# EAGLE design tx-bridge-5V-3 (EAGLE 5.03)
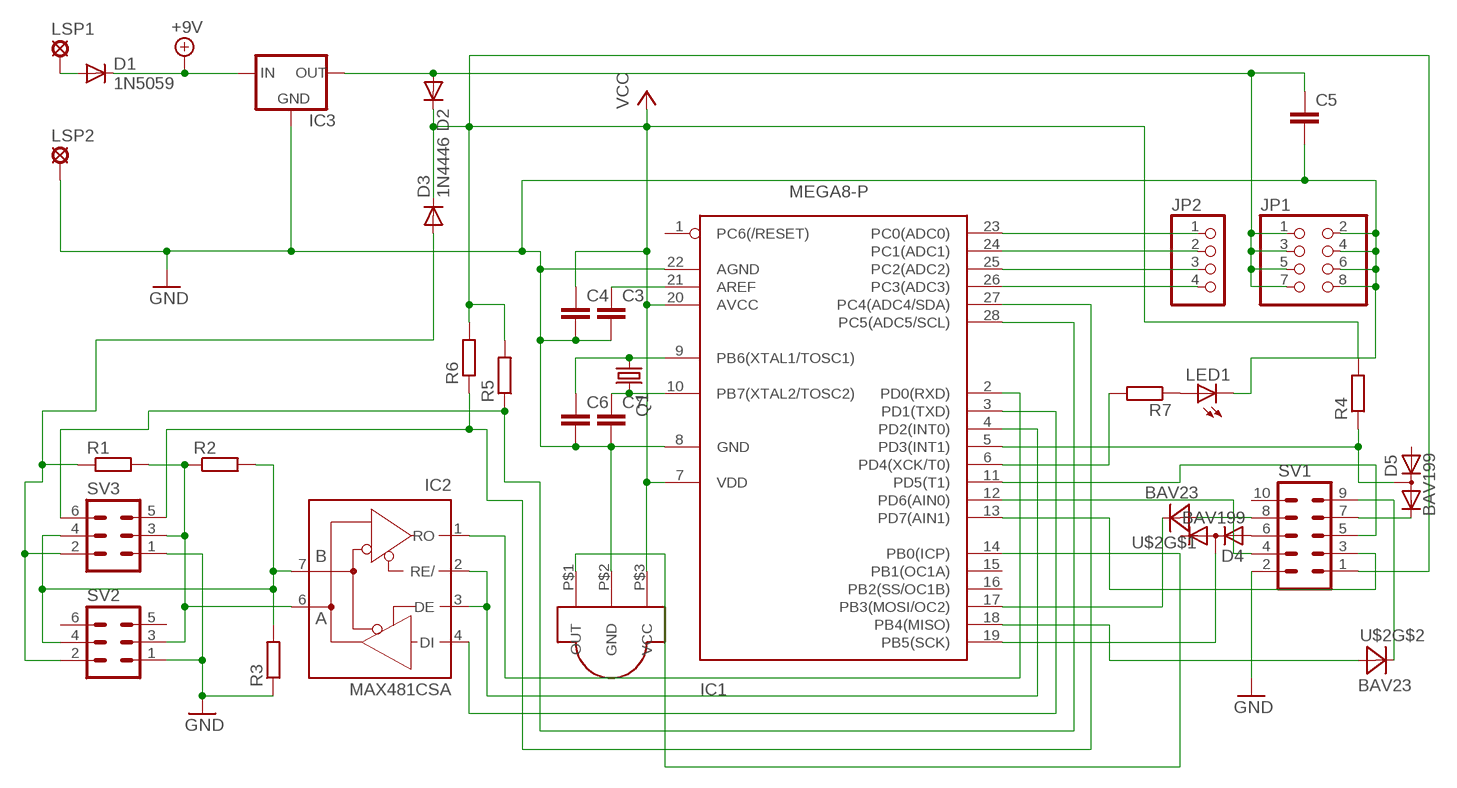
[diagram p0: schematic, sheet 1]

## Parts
C3  C-EUC0805  [C0805]
C4  C-EUC0805  [C0805]
C5  C-EUC0805  [C0805]
C6  C-EUC0805  [C0805]
C7  C-EUC0805  [C0805]
D1  1N5059  [DO204-10]
D2  DIODE-DO214AC  [DO214AC]
D3  1N4446  [DO35-10]
D4  BAV199  [SOT23]
D5  BAV199  [SOT23]
IC1  MEGA8-P  [DIL28-3]
IC2  MAX481CSA  [SO08]
IC3  78XXL  [78XXL]
JP1  PINHD-2X4  [2X04]
JP2  PINHD-1X4  [1X04]
LED1  LEDCHIP-LED0805  [CHIP-LED0805]
LSP1  LSP10  [LSP10]
LSP2  LSP10  [LSP10]
Q1  CRYSTALHC49S  [HC49/S]
R1  R-EU_R0805  [R0805]
R2  R-EU_R0805  [R0805]
R3  R-EU_R0805  [R0805]
R4  R-EU_R0805  [R0805]
R5  R-EU_R0805  [R0805]
R6  R-EU_R0805  [R0805]
R7  R-EU_R0805  [R0805]
SV1  ML10  [ML10]
SV2  ML6  [ML6]
SV3  ML6  [ML6]
U$1  SFH5110-XX  [SFH5110-XX]
U$2  BAV23  [SOT143-R]

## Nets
+9V: D1.C IC3.IN
GND: C3.2 C4.2 C5.2 C6.2 C7.2 IC1.8(GND) IC1.22(AGND) IC3.GND JP1.2 JP1.4 JP1.6 JP1.8 LED1.C LSP2.MP R3.1 SV1.2 SV2.1 SV3.1 U$1.P$2(GND)
N$1: D1.A LSP1.MP
N$3: C5.1 D2.A IC3.OUT JP1.1 JP1.3 JP1.5 JP1.7
N$4: D5.2(C) SV1.7
N$5: IC2.7(B) R2.2 R3.2 SV2.4 SV3.4
N$6: D3.A R1.1 SV2.2 SV3.2
N$7: IC2.6(A) R1.2 R2.1 SV2.3 SV3.3
N$8: C7.1 IC1.10(PB7(XTAL2/TOSC2)) Q1.2
N$9: C6.1 IC1.9(PB6(XTAL1/TOSC1)) Q1.1
N$10: D5.3(AC) IC1.5(PD3(INT1)) R4.1
N$12: IC1.4(PD2(INT0)) IC2.2(RE/) IC2.3(DE)
N$13: IC1.3(PD1(TXD)) IC2.4(DI)
N$14: IC1.2(PD0(RXD)) IC2.1(RO)
N$15: IC1.17(PB3(MOSI/OC2)) U$2.1(C)
N$16: D4.1(A) SV1.6
N$17: C3.1 IC1.21(AREF)
N$18: D4.3(AC) IC1.19(PB5(SCK))
N$19: IC1.12(PD6(AIN0)) SV1.4
N$20: IC1.23(PC0(ADC0)) JP2.1
N$21: IC1.24(PC1(ADC1)) JP2.2
N$22: IC1.25(PC2(ADC2)) JP2.3
N$23: IC1.26(PC3(ADC3)) JP2.4
N$24: IC1.13(PD7(AIN1)) SV1.3
N$25: IC1.11(PD5(T1)) SV1.5
N$26: IC1.18(PB4(MISO)) U$2.3(A)
N$27: IC1.27(PC4(ADC4/SDA)) R6.1 SV3.5
N$28: SV1.9 U$2.2(C)
N$29: IC1.28(PC5(ADC5/SCL)) R5.1 SV3.6
N$30: SV1.8 U$2.4(A)
N$31: IC1.14(PB0(ICP)) U$1.P$1(OUT)
N$32: LED1.A R7.1
N$33: IC1.6(PD4(XCK/T0)) R7.2
VCC: C4.1 D2.C D3.C IC1.7(VDD) IC1.20(AVCC) R4.2 R5.2 R6.2 SV1.1 U$1.P$3(VCC)
Unconnected: D4.2(C) D5.1(A) IC1.1(PC6(/RESET)) IC1.15(PB1(OC1A)) IC1.16(PB2(SS/OC1B)) SV1.10 SV2.5 SV2.6

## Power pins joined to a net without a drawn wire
GND: IC2.5(GND)
VCC: IC2.8(VCC)

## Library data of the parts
C3-C7 = rcl:C-EU: CAPACITOR, European symbol
D1 = diode:1N5059: DIODE
D2 = diode:DIODE-: DIODE
D3 = diode:1N4446: DIODE
D4 D5 = diode:BAV199: DIODE low-leakage double diode
IC1 = atmel:MEGA8-P: MICROCONTROLLER 8 Kbytes FLASH, 1 kbytes SRAM, 512 bytes EEPROM, USART, 4-channel 10 bit ADC, 2-channel 8 bit ADC Pin compatible with Atmega48, ATMega88, ATMega168 Source: avr.lbr
IC2 = maxim:MAX481CSA: RS485 TRANSEIVER
IC3 = v-reg-3:78XXL: VOLTAGE REGULATOR
JP1 = pinhead:PINHD-2X4: PIN HEADER
JP2 = pinhead:PINHD-1X4: PIN HEADER
LED1 = led:LED: LED
LSP1 LSP2 = solpad:LSP10: SOLDER PAD
Q1 = crystal:CRYSTAL: CRYSTAL
R1-R7 = rcl:R-EU_: RESISTOR, European symbol
SV1 = con-harting-ml:ML10: HARTING
SV2 SV3 = con-harting-ml:ML6: HARTING
U$1 = myown:SFH5110-XX
U$2 = diode:BAV23

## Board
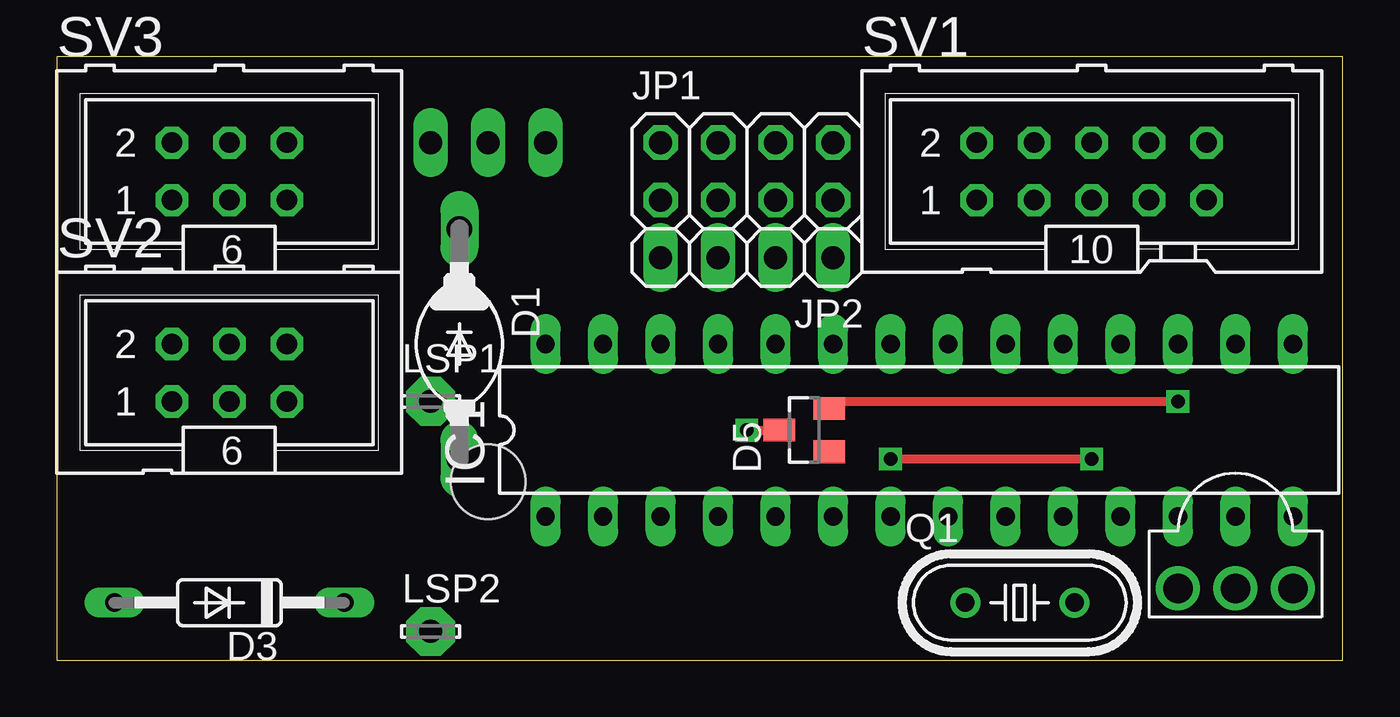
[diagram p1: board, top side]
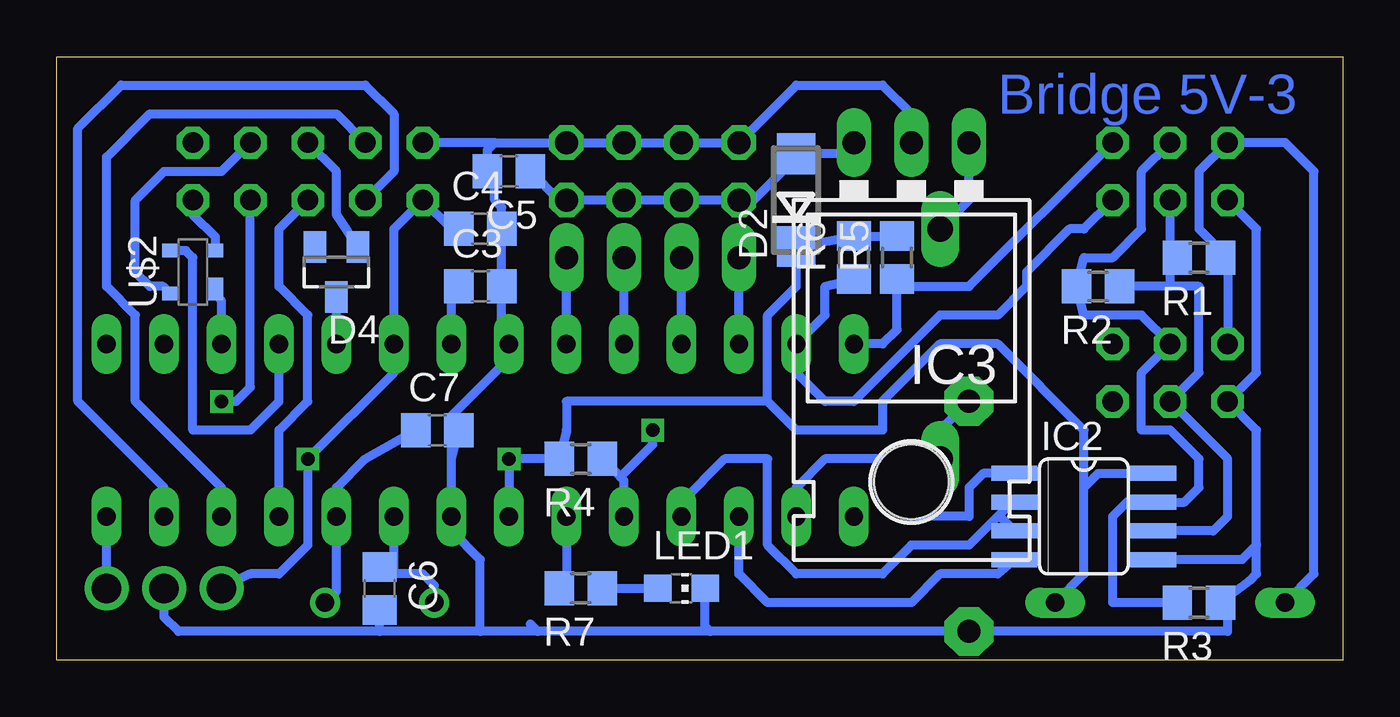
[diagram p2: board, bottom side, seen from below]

Size 56.82 x 26.66 mm. Coordinates in mm from the lower left corner, seen from the top.
Outline: 0,0 56.82,0 56.82,26.66 0,26.66 0,0
Copper layers (1*16): Top 0.035mm / dielectric 1.5mm / Bottom 0.035mm
Design rules "default": minimum track width 10mil, minimum drill 24mil, track to track 8mil, track to pad 8mil, pad to pad 8mil, via to via 8mil, smd to smd 8mil, copper to edge 40mil, drill to drill 8mil, minimum pad ring 10mil, minimum via ring 8mil, stop-mask expansion 4mil, vias tented up to drill 0mil, thermal gap 10mil

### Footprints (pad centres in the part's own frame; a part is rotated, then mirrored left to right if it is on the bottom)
C0805 = smd 1.3 x 1.5: 1 -0.95,0; 2 0.95,0
DO204-10 = drill 1.118 long: A 5.08,0; C -5.08,0
DO214AC = smd 1.8 x 1.7: A 2.05,0; C -2.05,0
DO35-10 = drill 0.813 long: A 5.08,0; C -5.08,0
SOT23 = smd 1 x 1.4: 1 -0.95,-1.1; 2 0.95,-1.1; 3 0,1.1
DIL28-3 = drill 0.813 long: 1 -16.51,-3.81; 2 -13.97,-3.81; 3 -11.43,-3.81; 4 -8.89,-3.81; 5 -6.35,-3.81; 6 -3.81,-3.81; 7 -1.27,-3.81; 8 1.27,-3.81; 9 3.81,-3.81; 10 6.35,-3.81; 11 8.89,-3.81; 12 11.43,-3.81; 13 13.97,-3.81; 14 16.51,-3.81; 15 16.51,3.81; 16 13.97,3.81; 17 11.43,3.81; 18 8.89,3.81; 19 6.35,3.81; 20 3.81,3.81; 21 1.27,3.81; 22 -1.27,3.81; 23 -3.81,3.81; 24 -6.35,3.81; 25 -8.89,3.81; 26 -11.43,3.81; 27 -13.97,3.81; 28 -16.51,3.81
SO08 = smd 0.66 x 2.032: 1 -1.905,-3.073; 2 -0.635,-3.073; 3 0.635,-3.073; 4 1.905,-3.073; 5 1.905,3.073; 6 0.635,3.073; 7 -0.635,3.073; 8 -1.905,3.073
78XXL = drill 1.016 long: GND 0,-3.81; IN -2.54,-3.81; OUT 2.54,-3.81 | hole 3.302: 0,11.176
2X04 = drill 1.016 octagon: 1 -3.81,-1.27; 2 -3.81,1.27; 3 -1.27,-1.27; 4 -1.27,1.27; 5 1.27,-1.27; 6 1.27,1.27; 7 3.81,-1.27; 8 3.81,1.27
1X04 = drill 1.016 long: 1 -3.81,0; 2 -1.27,0; 3 1.27,0; 4 3.81,0
CHIP-LED0805 = smd 1.2 x 1.2: A 0,-1.05; C 0,1.05
LSP10 = drill 1.016 pad 2.159 octagon: MP 0,0
HC49/S = drill 0.813 round: 1 -2.413,0; 2 2.413,0
R0805 = smd 1.3 x 1.5: 1 -0.95,0; 2 0.95,0
ML10 = drill 0.914 octagon: 1 -5.08,-1.27; 2 -5.08,1.27; 3 -2.54,-1.27; 4 -2.54,1.27; 5 0,-1.27; 6 0,1.27; 7 2.54,-1.27; 8 2.54,1.27; 9 5.08,-1.27; 10 5.08,1.27
ML6 = drill 0.914 octagon: 1 -2.54,-1.27; 2 -2.54,1.27; 3 0,-1.27; 4 0,1.27; 5 2.54,-1.27; 6 2.54,1.27
SFH5110-XX = drill 1.3 round: P$1 0,2.54; P$2 0,0; P$3 0,-2.54
SOT143-R = smd 1 x 0.7: 1 -0.75,-1 | smd 0.6 x 0.7: 2 0.95,-1; 3 0.95,1; 4 -0.95,1

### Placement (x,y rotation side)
C3  38.1,16.51 0 bottom
C4  38.1,19.05 0 bottom
C5  36.83,21.59 180 bottom
C6  42.55,3.17 270 bottom
C7  40.01,10.16 0 bottom
D1  17.78,13.97 270 top
D2  24.13,20.32 90 bottom
D3  7.62,2.54 180 top
D4  44.45,17.14 180 bottom
D5  33.02,10.16 90 top
IC1  38.1,10.16 0 top
IC2  11.43,6.35 270 bottom
IC3  19.05,19.05 180 bottom
JP1  30.48,21.59 0 top
JP2  30.48,17.78 180 top
LED1  29.21,3.17 270 bottom
LSP1  16.51,11.43 0 top
LSP2  16.51,1.27 0 top
Q1  42.55,2.54 0 top
R1  6.35,17.78 180 bottom
R2  10.79,16.51 180 bottom
R3  6.35,2.54 180 bottom
R4  33.66,8.89 180 bottom
R5  19.68,17.78 90 bottom
R6  21.59,17.78 90 bottom
R7  33.66,3.17 180 bottom
SV1  45.72,21.59 0 top
SV2  7.62,12.7 0 top
SV3  7.62,21.59 0 top
U$1  52.07,3.17 270 top
U$2  50.8,17.14 90 bottom

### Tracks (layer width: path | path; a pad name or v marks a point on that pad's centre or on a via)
+9V
  Bottom 0.406: D1.C 16.51,20.32 IC3.IN
GND
  Bottom 0.406: 39.37,8.89 IC1.8 39.37,5.71 38.1,4.45 38.1,1.27 | 27.94,1.27 LSP2.MP 5.08,1.27 5.08,2.54 R3.1 4.13,3.49 3.81,3.81 3.81,5.08 | 27.94,1.27 35.56,1.27 | 37.47,22.86 JP1.8 JP1.6 JP1.4 JP1.2 24.13,25.4 20.32,25.4 19.05,24.13 IC3.GND | 37.47,22.86 SV1.2 | 35.56,1.27 35.88,1.59 | 39.37,8.89 C7.2 | SV3.1 3.81,19.05 3.81,12.7 SV2.1 3.81,10.16 3.81,5.08 | IC2.5 4.45,4.45 3.81,5.08 | U$1.P$2 52.07,1.91 51.44,1.27 42.55,1.27 | 35.56,1.27 38.1,1.27 | 38.1,1.27 42.55,1.27 | 37.47,22.86 37.78,22.55 C5.2 37.47,21.27 37.47,20.32 37.15,20 C4.2 C3.2 37.15,14.29 IC1.22 36.83,13.34 39.37,10.79 39.37,8.89 | 42.55,1.27 C6.2 | LED1.C 28.16,1.49 27.94,1.27
N$1
  Bottom 0.406: LSP1.MP 17.78,10.16 D1.A
N$2  (via drill 0.6)
  other vias: 49.53,11.43
N$3
  Bottom 0.406: IC3.OUT 22.08,22.37 D2.A 24.13,22.23 26.04,20.32 JP1.1 JP1.3 JP1.5 JP1.7 34.61,20.32 C5.1
N$4  (via drill 0.6)
  Top 0.406: v49.53,11.43 34.44,11.43 D5.2
  Bottom 0.406: SV1.7 48.26,12.06 48.9,11.43 v49.53,11.43
N$5
  Bottom 0.406: SV3.4 8.89,21.59 8.89,19.05 10.16,17.78 11.43,17.78 R2.2 | R3.2 10.16,2.54 10.16,6.35 9.53,6.99 IC2.7 6.99,6.99 6.35,7.62 6.35,8.89 7.62,10.16 8.89,10.16 8.89,12.7 SV2.4 8.89,15.24 11.43,15.24 R2.2 | R2.2 11.43,16.19 | R2.2 11.43,16.83
N$6
  Bottom 0.406: 5.08,17.78 6.35,19.05 6.35,21.59 SV3.2 2.54,22.86 1.27,21.59 1.27,3.81 D3.A | 5.08,17.78 SV2.2 | 5.08,17.78 R1.1
N$7
  Bottom 0.406: 7.62,17.78 SV3.3 | IC2.6 5.71,5.71 5.08,6.35 5.08,8.89 SV2.3 6.35,12.7 6.35,16.51 7.62,16.51 | 7.62,16.51 R2.1 | 7.62,16.51 7.62,17.78 | R1.2 7.62,17.78
N$8
  Bottom 0.406: C7.1 43.18,8.89 44.45,7.62 IC1.10 44.45,3.05 Q1.2
N$9
  Bottom 0.406: 41.91,3.81 IC1.9 | Q1.1 40.13,3.3 40.64,3.81 41.91,3.81 | 41.91,3.81 42.23,3.81 C6.1
N$10  (via drill 0.6)
  Top 0.406: v30.48,10.16 D5.3
  Bottom 0.406: IC1.5 31.75,7.93 31.91,8.1 | 31.91,8.1 R4.1 | v30.48,10.16 30.48,9.53 31.91,8.1
N$11  (via drill 0.6)
  other vias: 45.72,8.89
N$12
  Bottom 0.406: 15.24,6.35 15.14,6.35 IC2.3 | IC2.2 14.61,6.99 15.24,6.35 | 15.24,6.35 16.51,5.08 19.05,5.08 20.32,3.81 24.13,3.81 25.4,5.08 25.4,8.89 27.3,8.89 29.21,6.99 IC1.4
N$13
  Bottom 0.406: IC1.3 26.67,3.81 25.4,2.54 19.05,2.54 17.78,3.81 15.24,3.81 IC2.4
N$14
  Bottom 0.406: IC2.1 15.88,8.26 16.51,7.62 16.51,6.35 19.05,6.35 20.32,8.89 22.86,8.89 24.13,7.62 IC1.2
N$15
  Bottom 0.406: U$2.1 49.8,16.14 49.53,15.88 IC1.17
N$16
  Bottom 0.406: SV1.6 44.45,21.59 44.45,19.68 D4.1
N$17
  Bottom 0.406: IC1.21 39.37,16.19 C3.1
N$18
  Bottom 0.406: IC1.19 D4.3
N$19
  Bottom 0.406: IC1.12 49.53,7.62 53.34,11.43 53.34,15.24 54.61,16.51 54.61,22.23 52.7,24.13 44.45,24.13 SV1.4
N$20
  Bottom 0.406: IC1.23 JP2.1
N$21
  Bottom 0.406: IC1.24 JP2.2
N$22
  Bottom 0.406: IC1.25 JP2.3
N$23
  Bottom 0.406: IC1.26 JP2.4
N$24
  Bottom 0.406: IC1.13 52.07,7.62 55.88,11.43 55.88,23.5 53.98,25.4 43.18,25.4 41.91,24.13 41.91,21.59 SV1.3
N$25
  Bottom 0.406: IC1.11 46.99,10.16 45.72,11.43 45.72,15.24 46.99,16.51 46.99,19.05 SV1.5
N$26
  Bottom 0.406: IC1.18 46.99,11.43 48.26,10.16 50.8,10.16 50.8,17.78 51.12,18.09 U$2.3
N$27
  Bottom 0.406: R6.1 22.86,16.51 22.86,15.24 IC1.27 24.13,12.7 22.86,11.43 21.59,11.43 17.78,15.24 15.24,15.24 13.97,16.51 13.97,17.14 12.06,19.05 11.43,19.05 SV3.5
N$28
  Bottom 0.406: U$2.2 49.8,18.68 50.8,19.68 SV1.9
N$29
  Bottom 0.406: IC1.28 20.32,13.97 19.68,14.61 R5.1 19.68,16.51 16.51,16.51 SV3.6
N$30
  Bottom 0.406: SV1.8 49.53,21.59 52.07,21.59 53.34,20.32 53.34,17.14 52.7,16.51 52.12,16.51 U$2.4
N$31
  Bottom 0.406: U$1.P$1 IC1.14
N$32
  Bottom 0.406: R7.1 LED1.A
N$33
  Bottom 0.406: IC1.6 34.29,3.49 R7.2
VCC  (via drill 0.6)
  Top 0.406: v36.83,8.89 v45.72,8.89
  Bottom 0.406: 8.26,8.26 IC2.8 10.79,8.26 11.43,7.62 | IC1.7 v36.83,8.89 R4.2 34.29,10.16 34.29,11.43 25.4,11.43 | U$1.P$3 48.26,3.81 46.99,3.81 45.72,5.08 v45.72,8.89 41.91,12.7 IC1.20 41.91,19.05 SV1.1 39.37,19.05 C4.1 | 25.4,11.43 24.13,10.16 20.32,10.16 20.32,11.43 17.78,13.97 15.24,13.97 11.43,10.16 11.43,7.62 | 11.43,7.62 11.43,3.81 D3.C | 25.4,11.43 25.4,15.24 24.13,16.51 D2.C R6.2 R5.2

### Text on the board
Bottom: Bridge 5V-3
